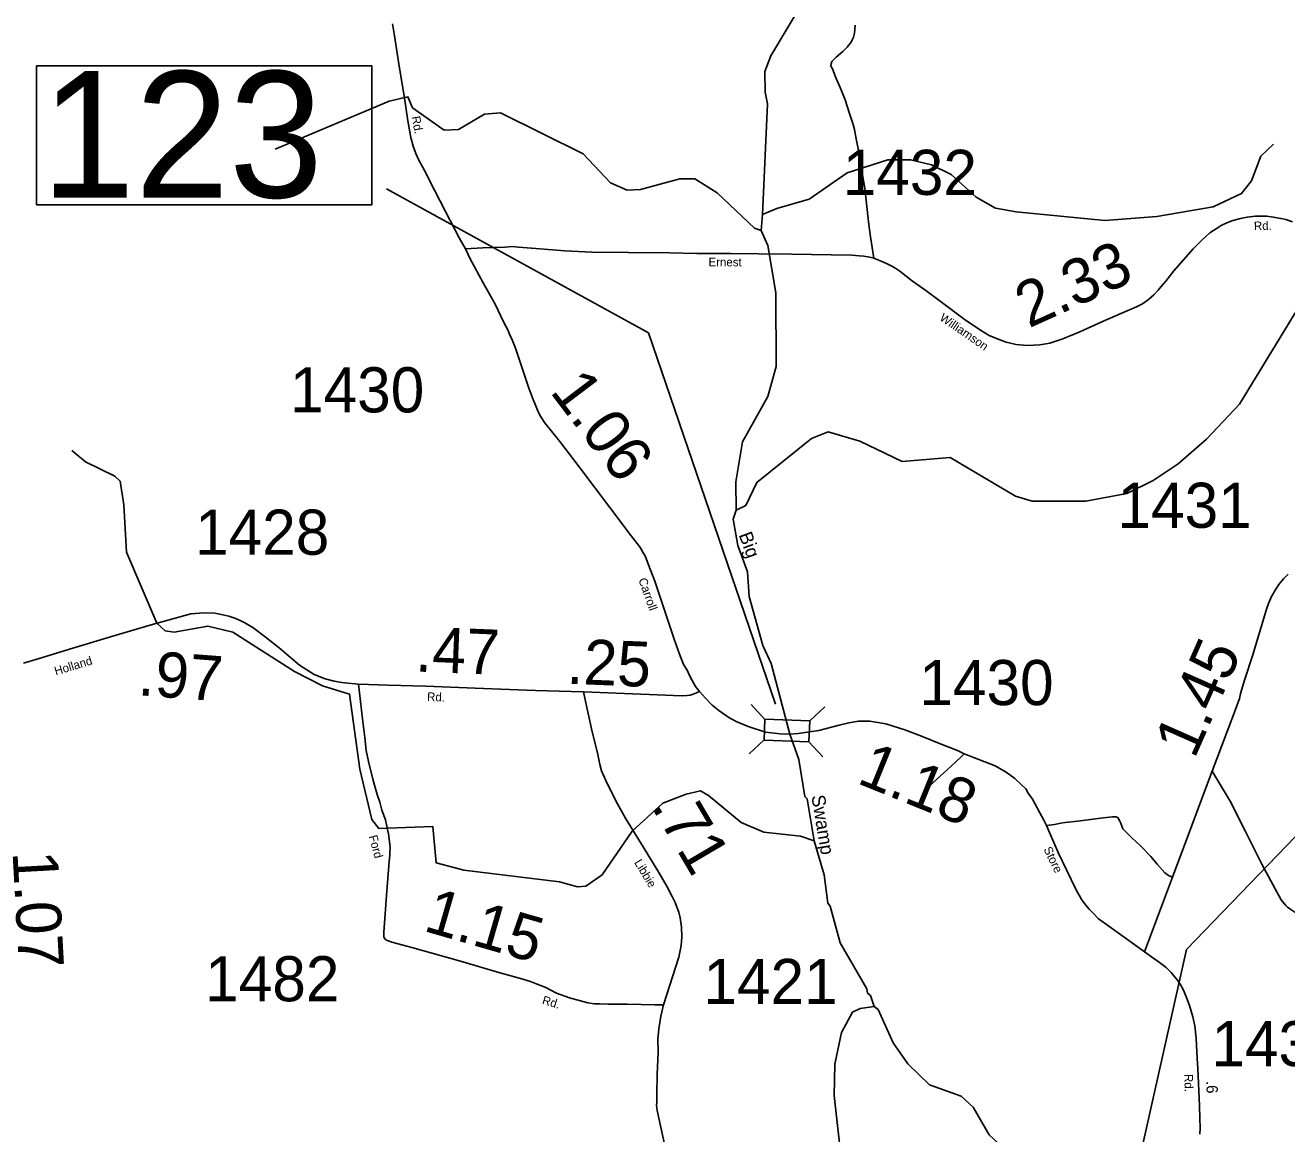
# Model space of a CAD drawing. Extents: x 2093524 to 2270757, y 289120 to 570408.
# Drawn here: x 2112932 to 2126907, y 473012 to 485292 of the extents above; entities that cross this region are included whole.
import ezdxf

# ---------------------------------------------------------------- set-up
doc = ezdxf.new("R2010")
doc.units = 0
for name, color, linetype in [('Exist Hydrographic Creek Single Shore', 7, 'Continuous'), ('Exist Hydrographic Misc Water Feature', 7, 'Continuous'), ('Exist Hydrographic Swamp Label', 7, 'Continuous'), ('Exist Road Non-System Type 51', 7, 'Continuous'), ('Exist Road Secondary Mileage Hundredths English Label', 7, 'Continuous'), ('Exist Road Secondary Structure Standard Bridge CELL', 7, 'Continuous'), ('Exist Road Secondary Structure Standard Bridge Number Label', 7, 'Continuous'), ('Exist Road Secondary Type 51 Attributed', 7, 'Continuous'), ('Exist Road Secondary Type 51 Label', 7, 'Continuous'), ('Exist Road Secondary Type 51 Number Label', 7, 'Continuous')]:
    doc.layers.add(name, color=color, linetype=linetype)

msp = doc.modelspace()

# ---------------------------------------------------------------- linework, layer by layer
at = {"layer": 'Exist Hydrographic Creek Single Shore'}
msp.add_line((2121084, 483018), (2121100, 483194), dxfattribs=at)
for points in [[(2121100, 483194), (2121153, 484420), (2121128, 484552), (2121127, 484778), (2121192, 484951), (2121722, 485846), (2121953, 486340), (2122017, 486821), (2122108, 487022), (2122224, 487190), (2123005, 487644), (2123653, 488205), (2123736, 488213)], [(2120806, 479920), (2120805, 480235), (2120878, 480676), (2121159, 481179), (2121249, 481512), (2121246, 482329), (2121160, 482852), (2121084, 483018)], [(2120806, 479920), (2120914, 479970), (2121038, 480227), (2121644, 480713), (2121827, 480788), (2122177, 480683), (2122645, 480460), (2123178, 480505), (2123904, 480074), (2124088, 480018), (2124680, 480019), (2125137, 480105), (2125428, 480247), (2125703, 480432), (2126019, 480708), (2126384, 481094), (2127376, 482721)], [(2121403, 477439), (2121197, 478222), (2121104, 478421), (2120952, 478962), (2120934, 479235), (2120825, 479529), (2120773, 479819), (2120806, 479920)], [(2121672, 476258), (2121595, 476722), (2121570, 476749), (2121501, 477157), (2121403, 477439)], [(2122338, 474420), (2122296, 474543), (2122263, 474570), (2122254, 474619), (2121960, 475127), (2121850, 475532), (2121825, 475566), (2121782, 475882), (2121672, 476258)], [(2125121, 471996), (2125106, 472298), (2125039, 472447), (2124947, 472521), (2124704, 472638), (2123937, 472735), (2123812, 472810), (2123611, 473001), (2123434, 473306), (2123301, 473430), (2122951, 473555), (2122708, 473786), (2122548, 474019), (2122381, 474387), (2122338, 474420)]]:
    msp.add_lwpolyline(points, dxfattribs=at)
at = {"layer": 'Exist Hydrographic Misc Water Feature'}
for points in [[(2121084, 483018), (2121009, 483045), (2120599, 483434), (2120349, 483590), (2120182, 483590), (2119749, 483471), (2119599, 483464), (2119416, 483546), (2119114, 483867), (2118196, 484322), (2118021, 484306), (2117730, 484138), (2117572, 484128), (2117221, 484378), (2117171, 484500), (2116963, 484452), (2115699, 483919)], [(2121100, 483194), (2121258, 483260), (2121616, 483364), (2122039, 483658), (2122489, 483800), (2122739, 483801), (2122972, 483744), (2123189, 483638), (2123465, 483386), (2123682, 483264), (2123908, 483223), (2124891, 483128), (2125467, 483172), (2126091, 483281), (2126407, 483426), (2126515, 483568), (2126621, 483841), (2126762, 483976)], [(2121672, 476258), (2121522, 476307), (2121113, 476354), (2120863, 476461), (2120503, 476760), (2120412, 476811), (2120253, 476775), (2119996, 476675), (2119655, 476364), (2119324, 475882), (2119142, 475754), (2119050, 475746), (2118850, 475802), (2117791, 475932), (2117483, 476014), (2117448, 476415), (2116848, 476394), (2116772, 476494), (2116637, 477051), (2116525, 477883), (2116224, 477974), (2115916, 478131), (2115230, 478568), (2114955, 478636), (2114581, 478568), (2114481, 478583), (2114389, 478667), (2114052, 479455), (2114025, 479980), (2113982, 480240), (2113923, 480297), (2113598, 480455), (2113447, 480579)], [(2119631, 470558), (2119430, 470798), (2119396, 470982), (2119478, 471115), (2119594, 471241), (2119802, 471309), (2120002, 471426), (2120693, 471429), (2121142, 471623), (2121474, 471941), (2121673, 472167), (2121806, 472250), (2121906, 472376), (2121970, 472742), (2121894, 473435), (2121899, 473783), (2121973, 474133), (2122098, 474360), (2122180, 474401), (2122338, 474420)]]:
    msp.add_lwpolyline(points, dxfattribs=at)
at = {"layer": 'Exist Road Non-System Type 51'}
for points in [[(2122126, 485294), (2122123, 485246), (2122120, 485204), (2122107, 485161), (2122095, 485139), (2122082, 485105), (2122036, 485048), (2121991, 485001), (2121916, 484938), (2121867, 484889), (2121860, 484865), (2121858, 484839), (2121874, 484809), (2121916, 484702), (2121960, 484601), (2122016, 484464), (2122061, 484324), (2122105, 484193), (2122118, 484135), (2122137, 484034), (2122166, 483888), (2122192, 483741), (2122212, 483613), (2122232, 483485), (2122247, 483353), (2122266, 483182), (2122279, 483086), (2122295, 482946), (2122331, 482713)], [(2123335, 477220), (2123298, 477182), (2123191, 477084), (2123067, 476974), (2122941, 476860)], [(2127614, 475071), (2127560, 475108), (2127458, 475174), (2127362, 475231), (2127252, 475301), (2127141, 475369), (2127062, 475422), (2126941, 475502), (2126915, 475521), (2126897, 475539), (2126844, 475604), (2126755, 475767), (2126631, 475999), (2126447, 476366), (2126279, 476697), (2126082, 477028)], [(2125641, 475856), (2125597, 475874), (2125557, 475901), (2125471, 475998), (2125400, 476082), (2125286, 476200), (2125192, 476291), (2125143, 476338), (2125092, 476391), (2125078, 476429), (2125065, 476459), (2125057, 476473), (2125035, 476514), (2125014, 476522), (2124978, 476522), (2124845, 476507), (2124709, 476491), (2124589, 476473), (2124453, 476459), (2124404, 476452), (2124334, 476439), (2124246, 476425)]]:
    msp.add_lwpolyline(points, dxfattribs=at)
at = {"layer": 'Exist Road Secondary Structure Standard Bridge CELL'}
for p, q in [((2121127, 477600), (2120973, 477766)), ((2121789, 477741), (2121623, 477587)), ((2121119, 477374), (2120953, 477220)), ((2121769, 477189), (2121614, 477355))]:
    msp.add_line(p, q, dxfattribs=at)
msp.add_lwpolyline([(2121614, 477355), (2121119, 477373), (2121127, 477604), (2121623, 477587)], close=True, dxfattribs=at)
at = {"layer": 'Exist Road Secondary Structure Standard Bridge Number Label'}
msp.add_lwpolyline([(2113057, 484841), (2116773, 484841), (2116773, 483304), (2113057, 483304)], close=True, dxfattribs=at)
for points in [[(2121242, 477769), (2119838, 481883), (2116935, 483480)], [(2125264, 472682), (2125797, 475053), (2127103, 476408)]]:
    msp.add_lwpolyline(points, dxfattribs=at)
at = {"layer": 'Exist Road Secondary Type 51 Attributed'}
for points in [[(2116999, 485309), (2117021, 485175), (2117068, 484888), (2117097, 484706), (2117130, 484509), (2117171, 484232), (2117204, 484048), (2117230, 483951), (2117259, 483871), (2117290, 483804), (2117356, 483681), (2117464, 483464), (2117589, 483230), (2117740, 482937), (2117808, 482814)], [(2117808, 482814), (2118002, 482825), (2118250, 482835), (2118328, 482841), (2118398, 482834), (2118588, 482819), (2118909, 482792), (2119207, 482779), (2119615, 482774), (2120073, 482769), (2120371, 482764), (2120749, 482763), (2121055, 482760), (2121423, 482756), (2121861, 482747), (2122089, 482745), (2122169, 482738), (2122223, 482733), (2122290, 482722), (2122331, 482713), (2122440, 482668), (2122482, 482649), (2122538, 482619), (2122577, 482597), (2122620, 482567), (2122762, 482458), (2122907, 482352), (2123067, 482235), (2123333, 482037), (2123513, 481914), (2123609, 481856), (2123710, 481813), (2123799, 481781), (2123909, 481754), (2124033, 481744), (2124173, 481753), (2124283, 481771), (2124428, 481817), (2124615, 481896), (2124857, 482006), (2125061, 482093), (2125244, 482173), (2125308, 482206), (2125374, 482253), (2125433, 482306), (2125481, 482356), (2125516, 482399), (2125567, 482458), (2125655, 482570), (2125871, 482814), (2125966, 482910), (2126056, 482992), (2126135, 483045), (2126181, 483072), (2126243, 483102), (2126310, 483128), (2126396, 483150), (2126469, 483165), (2126559, 483177), (2126627, 483178), (2126687, 483177), (2126757, 483166), (2126862, 483147), (2126898, 483138), (2126970, 483115)], [(2117808, 482814), (2117860, 482703), (2118005, 482437), (2118138, 482203), (2118234, 481997), (2118277, 481916), (2118296, 481870), (2118327, 481806), (2118363, 481713), (2118434, 481504), (2118510, 481273), (2118558, 481146), (2118583, 481083), (2118608, 481027), (2118633, 480973), (2118686, 480892), (2118854, 480681), (2119079, 480385), (2119408, 479950), (2119645, 479636), (2119735, 479517), (2119764, 479478), (2119770, 479460), (2119799, 479414), (2119838, 479315), (2119908, 479134), (2120017, 478802), (2120124, 478478), (2120179, 478325), (2120225, 478209), (2120264, 478146), (2120293, 478080), (2120359, 477967), (2120402, 477912)], [(2125331, 475029), (2125641, 475856), (2125854, 476426), (2126007, 476831), (2126082, 477028), (2126350, 477740), (2126371, 477803), (2126382, 477831), (2126395, 477889), (2126441, 478046), (2126526, 478307), (2126631, 478649), (2126682, 478824), (2126705, 478887), (2126739, 478965), (2126788, 479046), (2126819, 479098), (2126870, 479159), (2126921, 479212)], [(2112911, 478224), (2113085, 478275), (2113459, 478390), (2113878, 478516), (2114326, 478650), (2114766, 478771), (2114864, 478780), (2114950, 478784), (2115032, 478778), (2115120, 478761), (2115186, 478745), (2115252, 478725), (2115314, 478697), (2115366, 478670), (2115452, 478620), (2115589, 478518), (2115745, 478393), (2115970, 478204), (2116133, 478100), (2116253, 478053), (2116353, 478025), (2116441, 478012), (2116505, 478004), (2116587, 477996), (2116625, 477992)], [(2116625, 477992), (2116951, 477983), (2117368, 477969), (2118010, 477943), (2118586, 477922), (2118980, 477911), (2119116, 477908)], [(2116625, 477992), (2116667, 477608), (2116693, 477403), (2116710, 477256), (2116736, 477135), (2116781, 476941), (2116809, 476847), (2116830, 476771), (2116860, 476685), (2116884, 476597), (2116923, 476489), (2116943, 476399), (2116957, 476334), (2116964, 476279), (2116972, 476216), (2116974, 476178), (2116972, 476136), (2116970, 476098), (2116965, 476033), (2116953, 475888), (2116934, 475653), (2116903, 475245), (2116903, 475221), (2116903, 475205), (2116906, 475191), (2116913, 475177), (2116924, 475165), (2116933, 475158), (2116954, 475148), (2116993, 475136), (2117216, 475075), (2117753, 474923), (2118180, 474800), (2118420, 474731), (2118528, 474699), (2118604, 474670), (2118700, 474632), (2118819, 474569), (2118961, 474517), (2119165, 474464), (2119237, 474452), (2119299, 474452), (2119391, 474447), (2119601, 474447), (2119907, 474441), (2120004, 474439)], [(2119116, 477908), (2120024, 477872), (2120201, 477863), (2120264, 477866), (2120297, 477870), (2120330, 477883), (2120370, 477895), (2120402, 477912)], [(2120004, 474439), (2120172, 474968), (2120199, 475096), (2120207, 475192), (2120202, 475302), (2120186, 475402), (2120172, 475468), (2120147, 475534), (2120131, 475573), (2120097, 475641), (2120043, 475749), (2119950, 475907), (2119779, 476190), (2119586, 476501), (2119475, 476699), (2119362, 476925), (2119316, 477034), (2119299, 477104), (2119271, 477230), (2119214, 477464), (2119141, 477784), (2119116, 477908)], [(2120402, 477912), (2120467, 477837), (2120542, 477760), (2120615, 477702), (2120727, 477623), (2120807, 477577), (2120940, 477523), (2121134, 477461), (2121231, 477450), (2121290, 477441), (2121403, 477439)], [(2121403, 477439), (2121494, 477445), (2121723, 477478), (2121948, 477538), (2122057, 477565), (2122163, 477581), (2122289, 477583), (2122399, 477565), (2122466, 477552), (2122536, 477531), (2122677, 477486), (2122862, 477415), (2123079, 477326), (2123258, 477257), (2123335, 477220), (2123677, 477088), (2123800, 477018), (2123893, 476946), (2123969, 476877), (2124015, 476832), (2124044, 476786), (2124089, 476719), (2124118, 476669), (2124172, 476568), (2124215, 476485), (2124246, 476425), (2124277, 476350), (2124373, 476129), (2124518, 475828), (2124578, 475707), (2124638, 475604), (2124679, 475546), (2124717, 475499), (2124764, 475454), (2124823, 475393), (2124937, 475311), (2125082, 475207), (2125275, 475068), (2125331, 475029)], [(2125331, 475029), (2125410, 474970), (2125499, 474910), (2125572, 474853), (2125627, 474798), (2125676, 474741), (2125698, 474713), (2125725, 474668), (2125758, 474610), (2125789, 474539), (2125829, 474431), (2125867, 474306), (2125889, 474206), (2125905, 474069), (2125915, 473847), (2125921, 473735), (2125942, 473323), (2125946, 473181), (2125948, 473079), (2125943, 473009)], [(2120551, 469603), (2120562, 470023), (2120561, 470179), (2120547, 470277), (2120535, 470369), (2120520, 470453), (2120480, 470629), (2120437, 470837), (2120366, 471172), (2120290, 471544), (2120166, 472144), (2120054, 472675), (2120013, 472897), (2119934, 473271), (2119926, 473329), (2119929, 473361), (2119927, 473447), (2119934, 473669), (2119943, 473917), (2119941, 474059), (2119950, 474173), (2119972, 474313), (2120004, 474439)]]:
    msp.add_lwpolyline(points, dxfattribs=at)

# ---------------------------------------------------------------- texts
at = {"layer": 'Exist Hydrographic Swamp Label'}
for s, rotation, p in [('Big', 290.3127, (2120834, 479647)), ('Swamp', 279.4315, (2121640, 476753))]:
    msp.add_text(s, height=150, rotation=rotation, dxfattribs=at).set_placement(p)
at = {"layer": 'Exist Road Secondary Mileage Hundredths English Label'}
for s, height, rotation, p in [('2.33', 500, 24.4061, (2124049, 481932)), ('1.06', 500, 307.1452, (2118736, 481233)), ('.47', 500, 357.6357, (2117248, 478133)), ('.25', 500, 357.6811, (2118925, 477998)), ('1.45', 500, 66.1477, (2125883, 477154)), ('.97', 500, 355.6649, (2114172, 477871)), ('1.18', 500, 337.8945, (2122132, 476901)), ('.71', 500, 300.5034, (2119859, 476643)), ('1.07', 500, 273.1847, (2112791, 476133)), ('1.15', 500, 343.8793, (2117330, 475263)), ('.6', 125, 272.4497, (2126014, 473595))]:
    msp.add_text(s, height=height, rotation=rotation, dxfattribs=at).set_placement(p)
at = {"layer": 'Exist Road Secondary Structure Standard Bridge Number Label'}
msp.add_text('123', height=1400, dxfattribs=at).set_placement((2113107, 483383))
at = {"layer": 'Exist Road Secondary Type 51 Label'}
for s, rotation, p in [('Rd.', 280.2254, (2117212, 484277)), ('Rd.', 0.8431, (2126544, 483022)), ('Ernest', 359.7274, (2120501, 482622)), ('Williamson', 325.6474, (2123053, 482030)), ('Carroll', 289.6066, (2119723, 479150)), ('Holland', 16.8136, (2113271, 478089)), ('Rd.', 357.6357, (2117382, 477807)), ('Ford', 285.0738, (2116737, 476307)), ('Store', 295.6918, (2124211, 476164)), ('Libbie', 301.1456, (2119674, 476017)), ('Rd.', 343.3201, (2118651, 474452)), ('Rd.', 270.8993, (2125773, 473673))]:
    msp.add_text(s, height=95, rotation=rotation, dxfattribs=at).set_placement(p)
at = {"layer": 'Exist Road Secondary Type 51 Number Label'}
for s, p in [('1432', (2121988, 483412)), ('1430', (2115865, 481003)), ('1431', (2125032, 479724)), ('1428', (2114813, 479426)), ('1430', (2122837, 477760)), ('1482', (2114925, 474479)), ('1421', (2120445, 474449)), ('1430', (2126072, 473760))]:
    msp.add_text(s, height=500, dxfattribs=at).set_placement(p)

doc.saveas('drawing.dxf')
